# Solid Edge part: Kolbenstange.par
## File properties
Username: ahadarics
Dokumentum tartalom típus: 0
Author: ahadarics
Last saved by: ahadarics
Revision: 88
Sűrűség: 0,000 kg/m^3
Pontosság: 0,990
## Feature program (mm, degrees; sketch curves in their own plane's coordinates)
base feature "unnamed BaseFeature 1"
thread "unnamed Thread 1"
chamfer "Letörés_1" setback 0.7
sketch for "Kihúzás_1" plane through (43.75, 0, 0) normal (1, 0, 0) x-axis (0, -1, 0)
  circle centre (0, 0) radius 10
extrude "Kihúzás_1" add finite 16 along -normal
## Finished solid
Body 1: solid body, 13 faces, 23 edges, 12 vertices.
  Faces by surface: plane 9, cylinder 3, cone 1
  Edges by curve: line 12, circle 11
Bounding box of the edges (mm): 477.500 x 20.000 x 20.000, from (-433.75, -10, -10) to (43.75, 10, 10).
Cylindrical faces by radius (mm): R4 x2, R10 x1
Conical faces (half-angle, radius in mm at the cone's reference point): 45 deg R3.3 x1
Planar faces by outward normal: +x 3, +z 1, -x 4, -z 1
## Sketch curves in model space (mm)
circle centre (43.75, 0, 0) radius 10
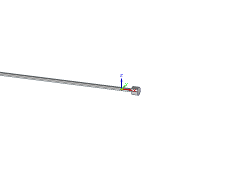
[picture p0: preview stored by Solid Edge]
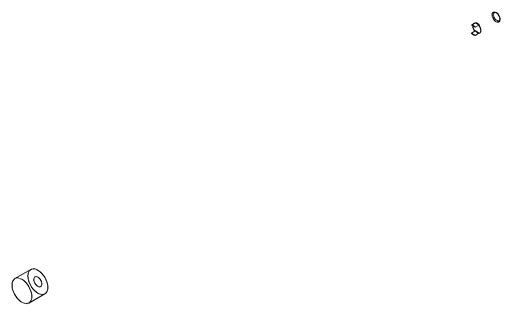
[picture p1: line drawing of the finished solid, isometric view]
